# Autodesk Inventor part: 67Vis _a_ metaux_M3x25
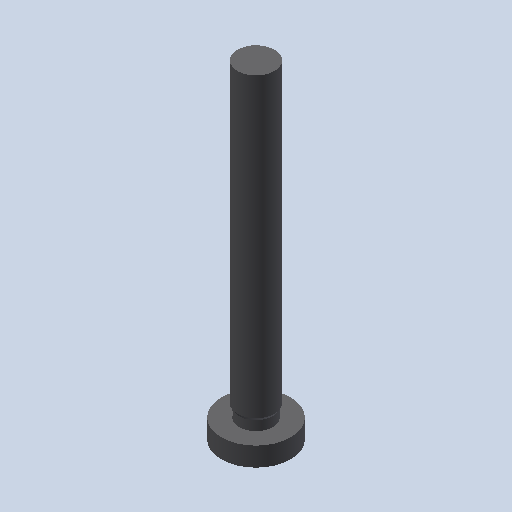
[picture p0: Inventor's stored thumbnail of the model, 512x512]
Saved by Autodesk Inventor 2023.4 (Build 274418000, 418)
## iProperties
Created: 2011-01
Part Number: 67Vis _a_ metaux_M3x25
Document SubType Name: Modeling
Designer: eric
Density: 1 g/cm^3
Mass: 0.220255 g
Surface Area: 3.25153 cm^2
Volume: 0.220255 cm^3
Material: Générique
Appearance: Red
Author: eric
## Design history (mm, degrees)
feature "Base1"
node "Corps solides"
node "Corps surfaciques"
node "Solide1"
